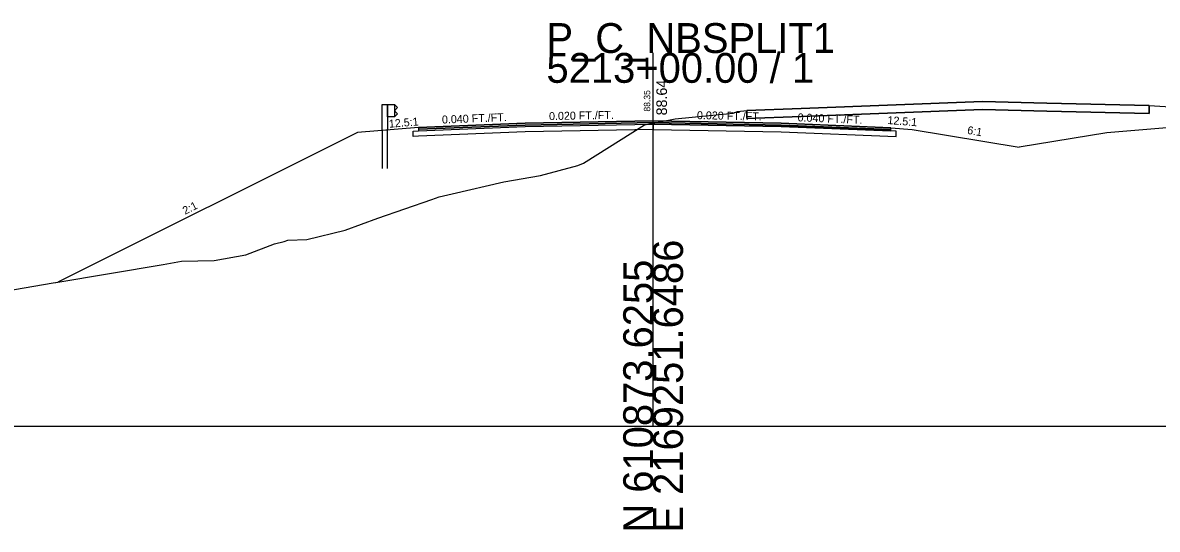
# Model space of a CAD drawing. Extents: x -26 to 1303, y -3010 to 12038.
# Drawn here: x 1090.9 to 1197.3, y 7490.3 to 7537.8 of the extents above; entities that cross this region are included whole.
import ezdxf

# ---------------------------------------------------------------- set-up
doc = ezdxf.new("R2010")
doc.units = 0
for name, color, linetype in [('RD_GPK_XS_Cell', 7, 'Continuous'), ('RD_PD_Final_TrvlWay', 7, 'Continuous'), ('RD_XS_Base', 7, 'Continuous'), ('RD_XS_ExGround', 7, 'Continuous'), ('RD_XS_ExPaveRet', 7, 'Continuous'), ('RD_XS_GR', 7, 'Continuous'), ('RD_XS_Greenside', 7, 'Continuous'), ('RD_XS_Pave', 7, 'Continuous'), ('RD_XS_PaveOvlay_CP', 7, 'Continuous'), ('RD_XS_TieSlope', 7, 'Continuous'), ('RD_XS_TX_Elev_EX', 7, 'Continuous'), ('RD_XS_TX_Elev_PR', 7, 'Continuous'), ('RD_XS_TX_ShdSlope', 7, 'Continuous'), ('RD_XS_TX_Slope', 7, 'Continuous')]:
    doc.layers.add(name, color=color, linetype=linetype)

msp = doc.modelspace()

# ---------------------------------------------------------------- linework, layer by layer
at = {"layer": 'RD_GPK_XS_Cell'}
for p, q in [((1150, 7500), (1150, 7535)), ((1000, 7500), (1150, 7500)), ((1150, 7500), (1300, 7500))]:
    msp.add_line(p, q, dxfattribs=at)
at = {"layer": 'RD_PD_Final_TrvlWay'}
for p, q in [((1125.11, 7527.77), (1124.61, 7527.73)), ((1124.61, 7527.73), (1124.61, 7524.17)), ((1125.11, 7524.17), (1125.11, 7527.77))]:
    msp.add_line(p, q, dxfattribs=at)
at = {"layer": 'RD_XS_Base'}
for p, q in [((1128, 7527.69), (1138, 7528.09)), ((1138, 7528.09), (1150, 7528.33)), ((1138, 7528.09), (1138, 7528.09)), ((1150, 7528.33), (1150, 7528.49)), ((1150, 7528.49), (1150, 7527.83)), ((1150, 7528.33), (1150, 7527.83)), ((1162, 7528.09), (1150, 7528.33)), ((1150, 7528.33), (1150, 7528.33)), ((1172.27, 7527.68), (1162, 7528.09)), ((1127.5, 7527.67), (1128, 7527.69)), ((1127.5, 7527.17), (1127.5, 7527.67)), ((1127.5, 7527.67), (1127.5, 7527.67)), ((1128, 7527.19), (1127.5, 7527.17)), ((1127.5, 7527.17), (1127.5, 7527.17)), ((1127.5, 7527.17), (1127.5, 7527.17)), ((1128, 7527.69), (1128, 7527.69)), ((1138, 7527.59), (1128, 7527.19)), ((1128, 7527.19), (1128, 7527.19)), ((1150, 7527.83), (1138, 7527.59)), ((1138, 7527.59), (1138, 7527.59)), ((1150, 7527.83), (1150, 7527.83)), ((1150, 7527.83), (1150, 7527.83)), ((1150, 7527.83), (1162, 7527.59)), ((1162, 7527.59), (1172.77, 7527.16)), ((1164, 7528.01), (1164, 7528.01)), ((1164, 7527.51), (1164, 7527.51)), ((1172.77, 7527.66), (1172.27, 7527.68)), ((1172.27, 7527.68), (1172.27, 7527.68)), ((1172.77, 7527.16), (1172.77, 7527.66)), ((1172.77, 7527.66), (1172.77, 7527.66)), ((1172.77, 7527.16), (1172.77, 7527.16)), ((1172.77, 7527.16), (1172.77, 7527.16))]:
    msp.add_line(p, q, dxfattribs=at)
at = {"layer": 'RD_XS_ExGround'}
msp.add_lwpolyline([(1025.24, 7501.62), (1093.77, 7513.43), (1093.99, 7513.47), (1094.03, 7513.47), (1104.08, 7515.16), (1105.81, 7515.48), (1108.86, 7515.54), (1111.84, 7516.05), (1114.51, 7517.08), (1115.43, 7517.31), (1115.77, 7517.43), (1117.55, 7517.49), (1121.12, 7518.36), (1124.2, 7519.5), (1129.27, 7521.26), (1129.94, 7521.49), (1131.16, 7521.78), (1136.02, 7522.92), (1139.44, 7523.49), (1142.94, 7524.45), (1143.48, 7524.67), (1149.2, 7528.26), (1152.05, 7528.81), (1157.51, 7529.34), (1157.91, 7529.5), (1158.79, 7529.59), (1163.86, 7529.79), (1180.87, 7530.45), (1186.91, 7530.3), (1196.49, 7530.08), (1200.03, 7529.84)], dxfattribs=at)
at = {"layer": 'RD_XS_ExPaveRet'}
msp.add_line((1180.87, 7530.45), (1163.86, 7529.79), dxfattribs=at)
for points in [[(1196.49, 7530.08), (1196.49, 7529.33), (1196.49, 7529.33), (1196.49, 7529.33), (1196.49, 7529.33), (1186.91, 7529.55), (1186.91, 7529.55), (1180.87, 7529.7), (1180.87, 7529.7), (1163.86, 7529.04), (1163.86, 7529.04), (1158.79, 7528.84), (1158.79, 7528.84), (1158.79, 7529.59), (1158.79, 7529.59), (1158.79, 7529.59), (1163.86, 7529.79), (1163.86, 7529.79), (1180.87, 7530.45), (1180.87, 7530.45), (1186.91, 7530.3), (1186.91, 7530.3), (1196.49, 7530.08), (1196.49, 7530.08), (1196.49, 7530.08)], [(1163.86, 7529.79), (1158.79, 7529.59), (1158.79, 7529.59), (1158.79, 7528.84), (1158.79, 7528.84), (1163.86, 7529.04), (1180.87, 7529.7), (1186.91, 7529.55), (1196.49, 7529.33), (1196.49, 7529.33), (1196.49, 7530.08), (1186.91, 7530.3), (1180.87, 7530.45)]]:
    msp.add_lwpolyline(points, dxfattribs=at)
at = {"layer": 'RD_XS_GR'}
for points in [[(1125.11, 7530.17), (1125.11, 7527.77), (1124.61, 7527.73), (1124.61, 7530.17), (1124.86, 7530.17), (1125.11, 7530.17)], [(1125.77, 7530.17), (1125.77, 7529), (1125.11, 7529), (1125.11, 7530.17), (1125.77, 7530.17)], [(1126.04, 7529.88), (1125.77, 7530.17), (1125.77, 7529), (1125.77, 7529), (1125.77, 7529), (1126.04, 7529.29), (1126.04, 7529.29), (1125.77, 7529.58), (1125.77, 7529.58), (1126.04, 7529.88), (1126.04, 7529.88)]]:
    msp.add_lwpolyline(points, dxfattribs=at)
at = {"layer": 'RD_XS_Greenside'}
for p, q in [((1122.29, 7527.55), (1094.2, 7513.5)), ((1174.27, 7527.83), (1184.32, 7526.16)), ((1192.52, 7527.52), (1184.32, 7526.16))]:
    msp.add_line(p, q, dxfattribs=at)
at = {"layer": 'RD_XS_Pave'}
for p, q in [((1138, 7528.4), (1128, 7528)), ((1138, 7528.24), (1128, 7527.85)), ((1128, 7527.85), (1138, 7528.24)), ((1128, 7527.69), (1138, 7528.09)), ((1150, 7528.64), (1138, 7528.4)), ((1150, 7528.49), (1138, 7528.24)), ((1138, 7528.24), (1150, 7528.49)), ((1138, 7528.4), (1138, 7528.4)), ((1138, 7528.09), (1150, 7528.33)), ((1138, 7528.24), (1138, 7528.24)), ((1138, 7528.24), (1138, 7528.24)), ((1138, 7528.09), (1138, 7528.09)), ((1162, 7528.4), (1150, 7528.64)), ((1150, 7528.33), (1150, 7528.49)), ((1150, 7528.49), (1162, 7528.24)), ((1162, 7528.24), (1150, 7528.49)), ((1150, 7528.49), (1150, 7528.33)), ((1150, 7528.33), (1150, 7528.33)), ((1150, 7528.33), (1150, 7528.33)), ((1150, 7528.33), (1162, 7528.09)), ((1172.27, 7527.99), (1162, 7528.4)), ((1162, 7528.24), (1172.27, 7527.83)), ((1172.27, 7527.83), (1162, 7528.24)), ((1162, 7528.09), (1172.27, 7527.68)), ((1164, 7528.32), (1164, 7528.32)), ((1164, 7528.16), (1164, 7528.16)), ((1164, 7528.16), (1164, 7528.16)), ((1128, 7528), (1128, 7528)), ((1128, 7528), (1128, 7527.85)), ((1128, 7527.85), (1128, 7527.85)), ((1128, 7527.85), (1128, 7527.69)), ((1128, 7527.85), (1128, 7527.85)), ((1128, 7527.85), (1128, 7527.85)), ((1128, 7527.69), (1128, 7527.69)), ((1128, 7527.69), (1128, 7527.69)), ((1164, 7528.01), (1164, 7528.01)), ((1172.27, 7527.83), (1172.27, 7527.99)), ((1172.27, 7527.99), (1172.27, 7527.99)), ((1172.27, 7527.83), (1172.27, 7527.83)), ((1172.27, 7527.83), (1172.27, 7527.83)), ((1172.27, 7527.68), (1172.27, 7527.83)), ((1172.27, 7527.83), (1172.27, 7527.83)), ((1172.27, 7527.68), (1172.27, 7527.68)), ((1172.27, 7527.68), (1172.27, 7527.68))]:
    msp.add_line(p, q, dxfattribs=at)
at = {"layer": 'RD_XS_PaveOvlay_CP'}
for p, q in [((1128, 7528), (1138, 7528.4)), ((1138, 7528.4), (1150, 7528.64)), ((1150, 7528.64), (1162, 7528.4)), ((1162, 7528.4), (1172.27, 7527.99))]:
    msp.add_line(p, q, dxfattribs=at)
at = {"layer": 'RD_XS_TieSlope'}
for p, q in [((1128, 7528), (1122.29, 7527.55)), ((1172.27, 7527.99), (1174.27, 7527.83)), ((1198.52, 7528), (1192.52, 7527.52))]:
    msp.add_line(p, q, dxfattribs=at)

# ---------------------------------------------------------------- texts
at = {"layer": 'RD_GPK_XS_Cell'}
for s, p in [('P_C_NBSPLIT1', (1140, 7535)), ('5213+00.00 / 1', (1140, 7532.2))]:
    msp.add_text(s, height=2.8, dxfattribs=at).set_placement(p)
for s, p in [('E 2169251.6486', (1152.8, 7490)), ('N 610873.6255', (1150, 7490))]:
    msp.add_text(s, height=2.8, rotation=90, dxfattribs=at).set_placement(p)
at = {"layer": 'RD_XS_TX_Elev_EX'}
msp.add_text('88.35', height=0.6, rotation=90, dxfattribs=at).set_placement((1149.73, 7529.5))
at = {"layer": 'RD_XS_TX_Elev_PR'}
msp.add_text('88.64', height=1, rotation=90, dxfattribs=at).set_placement((1151.3, 7529.14))
at = {"layer": 'RD_XS_TX_ShdSlope'}
for rotation, p in [(4.5739, (1125.26, 7527.98)), (355.4261, (1171.94, 7528.34))]:
    msp.add_text('12.5:1', height=0.75, rotation=rotation, dxfattribs=at).set_placement(p)
at = {"layer": 'RD_XS_TX_Slope'}
for s, rotation, p in [('0.040 FT./FT.', 2.2906, (1130.22, 7528.37)), ('0.020 FT./FT.', 1.1458, (1140.25, 7528.7)), ('0.020 FT./FT.', 358.8542, (1154.1, 7528.79)), ('0.040 FT./FT.', 357.7094, (1163.53, 7528.59)), ('6:1', 350.5377, (1179.4, 7527.41)), ('2:1', 26.5651, (1106.13, 7519.81))]:
    msp.add_text(s, height=0.75, rotation=rotation, dxfattribs=at).set_placement(p)

doc.saveas('drawing.dxf')
